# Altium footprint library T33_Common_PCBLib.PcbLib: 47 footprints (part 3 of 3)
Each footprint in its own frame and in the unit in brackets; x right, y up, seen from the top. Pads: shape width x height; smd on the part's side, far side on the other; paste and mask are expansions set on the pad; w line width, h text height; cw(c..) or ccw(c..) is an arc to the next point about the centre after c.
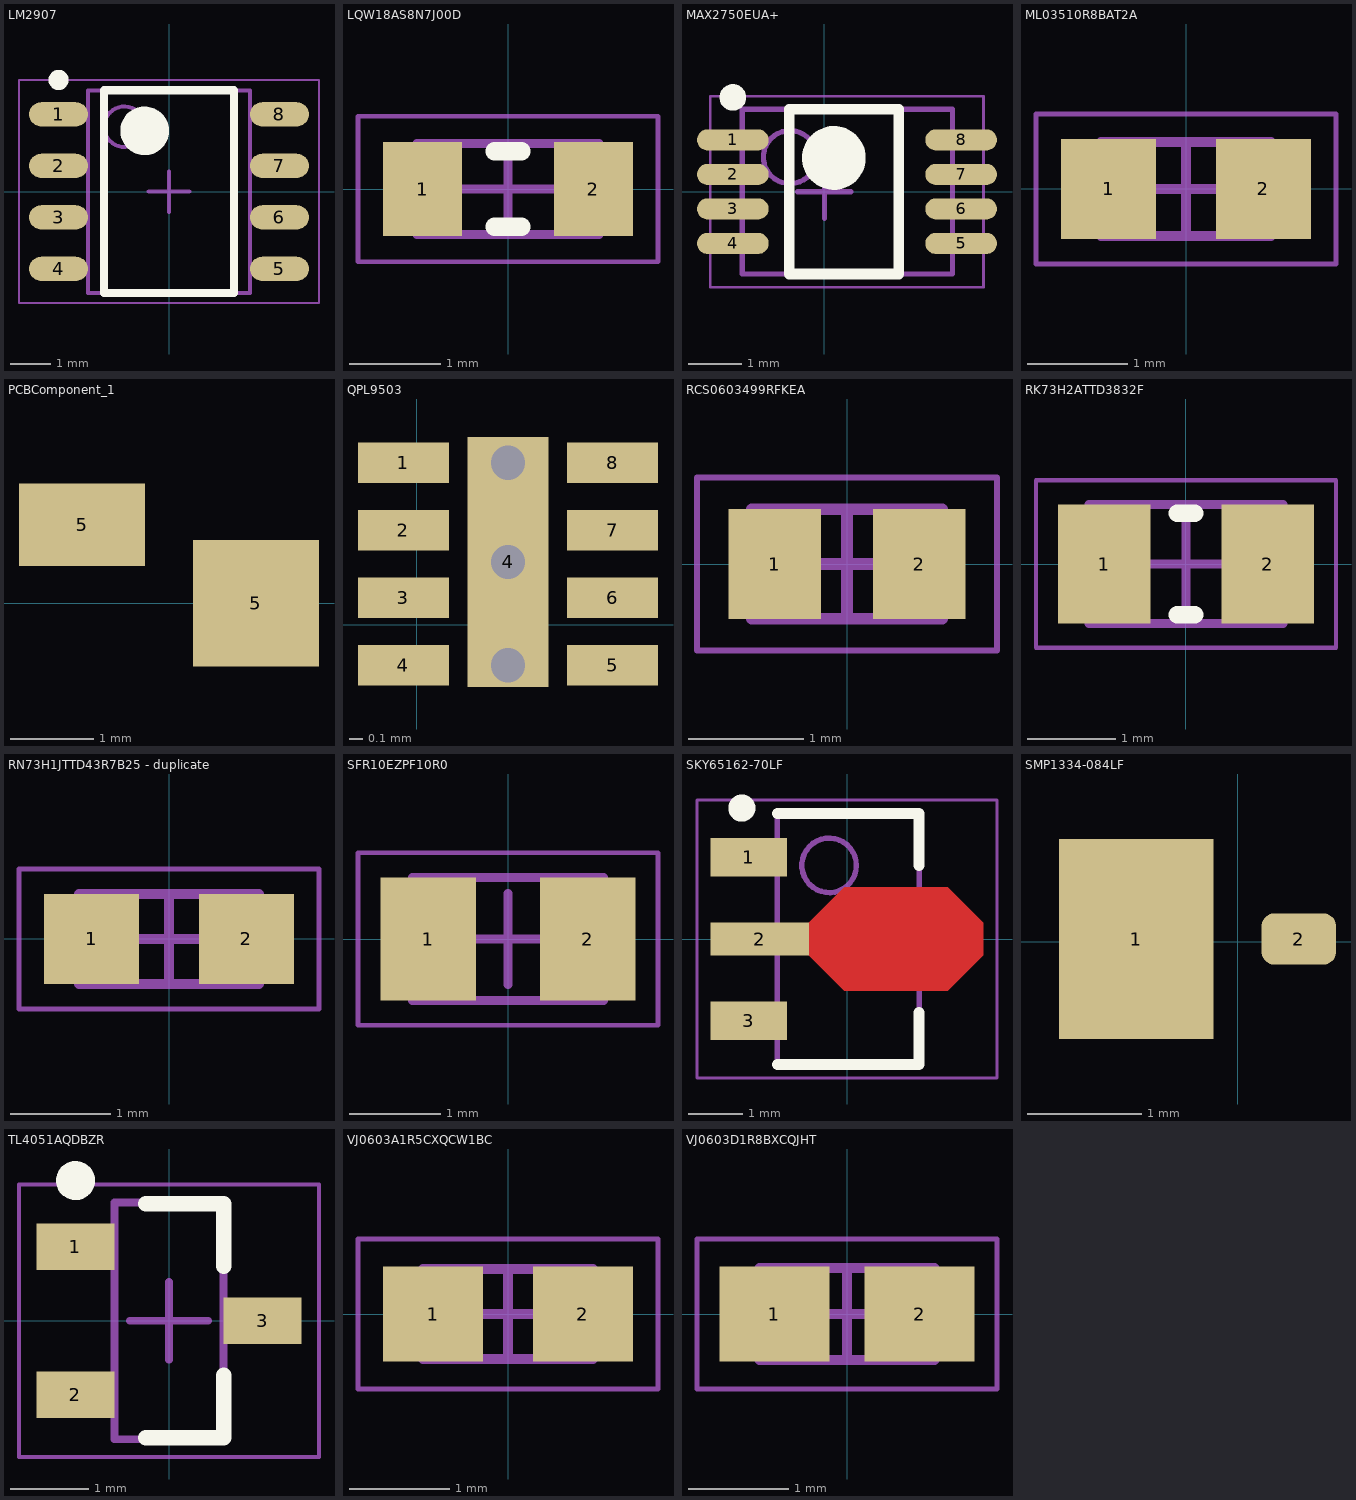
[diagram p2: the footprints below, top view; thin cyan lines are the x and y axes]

## LM2907 [mm] "Frequency to Voltage Converter"
height 1.75
pads (8):
  oval 1.45x0.6 smd: 1(-2.725,1.905) 2(-2.725,0.635) 3(-2.725,-0.635) 4(-2.725,-1.905) 5(2.725,-1.905) 6(2.725,-0.635) 7(2.725,0.635) 8(2.725,1.905)
Top Overlay:
  circle w0.25: c-2.725,2.755 r0.125
  circle w0.6: c-0.6,1.5 r0.3
  lines w0.2: -1.6,-2.5 -1.6,2.5 1.6,2.5 1.6,-2.5 -1.6,-2.5
Mechanical 13:
  circle w0.1: c-1.1,1.6 r0.5
  lines w0.1: -2,-2.5 -2,2.5 2,2.5 2,-2.5 -2,-2.5
Mechanical 15:
  lines w0.05: -3.7,-2.75 -3.7,2.75 3.7,2.75 3.7,-2.75 -3.7,-2.75
  lines w0.1: -0.5,0 0.5,0 ; 0,-0.5 0,0.5
3D body: height 1.75, standoff 0.1, extent -2,-2.5 2,2.5

## LQW18AS8N7J00D [mm] "8.7nH 0603"
height 0.94
pads (2):
  rect 0.87x1.03 smd: 1(-0.94,0) 2(0.94,0)
Top Overlay:
  lines w0.2: -0.15,-0.415 0.15,-0.415 ; -0.15,0.415 0.15,0.415
Mechanical 13:
  lines w0.1: -1,-0.5 1,-0.5 1,0.5 -1,0.5 -1,-0.5
Mechanical 15:
  lines w0.05: -1.65,-0.8 1.65,-0.8 1.65,0.8 -1.65,0.8 -1.65,-0.8
  lines w0.1: -0.5,0 0.5,0 ; 0,-0.5 0,0.5
3D body: height 0.94, standoff 0, extent 0.65,-0.5 1,0.5
3D body: height 0.94, standoff 0, extent -1,-0.5 -0.65,0.5
3D body: height 0.94, standoff 0, extent -0.65,-0.5 0.65,0.5

## MAX2750EUA+ [mm] "VCO Oscillators 2.4Ghz Monolithic Voltage-Controlled Oscillators"
height 1.1
pads (8):
  oval 1.35x0.4 smd: 1(-1.725,0.975) 2(-1.725,0.325) 3(-1.725,-0.325) 4(-1.725,-0.975) 5(2.575,-0.975) 6(2.575,-0.325) 7(2.575,0.325) 8(2.575,0.975)
Top Overlay:
  circle w0.6: c0.178,0.635 r0.3
  circle w0.25: c-1.725,1.775 r0.125
  lines w0.2: -0.66,-1.55 1.397,-1.55 1.397,1.55 -0.66,1.55 -0.66,-1.55
Mechanical 13:
  circle w0.1: c-0.65,0.65 r0.5
  lines w0.1: -1.55,-1.55 -1.55,1.55 2.413,1.55 2.413,-1.55 -1.55,-1.55
Mechanical 15:
  lines w0.05: -2.15,-1.8 2.997,-1.8 2.997,1.8 -2.15,1.8 -2.15,-1.8
  lines w0.1: -0.5,0 0.5,0 ; 0,-0.5 0,0.5
3D body: height 1.1, standoff 0.15, extent -1.55,-1.55 2.413,1.55

## ML03510R8BAT2A [mm] "MLCC - SMD/SMT 50V 0.8pF C0G 0603 0.1pF"
height 0.94
pads (2):
  rect 0.95x1 smd: 1(-0.775,0) 2(0.775,0)
Mechanical 13:
  lines w0.1: -0.85,-0.47 0.85,-0.47 0.85,0.47 -0.85,0.47 -0.85,-0.47
Mechanical 15:
  lines w0.05: -1.5,-0.75 1.5,-0.75 1.5,0.75 -1.5,0.75 -1.5,-0.75
  lines w0.1: -0.47,0 0.47,0 ; 0,-0.47 0,0.47
3D body: height 0.94, standoff 0, extent 0.5,-0.47 0.85,0.47
3D body: height 0.94, standoff 0, extent -0.85,-0.47 -0.5,0.47
3D body: height 0.94, standoff 0, extent -0.5,-0.47 0.5,0.47

## PCBComponent_1 [mm]
pads (2):
  rect 1.524x1 smd: 5(-3.15,0.95)
  rect 1.524x1.524 smd: 5(-1.05,0)

## QPL9503 [mm] "Ultra Low-Noise, Flat Gain LNA"
pads (9):
  rect 0.674x0.3 smd: 1(-0.1,1.2) 2(-0.1,0.7) 3(-0.1,0.2) 4(-0.1,-0.3) 5(1.45,-0.3) 6(1.45,0.2) 7(1.45,0.7) 8(1.45,1.2)
  rect 0.6x1.85 smd: 4(0.675,0.465)
via 0.675,0.465 diameter 0.254 hole 0.254
via 0.675,1.2 diameter 0.254 hole 0.254
via 0.675,-0.3 diameter 0.254 hole 0.254

## RCS0603499RFKEA [mm] "Thick Film Resistors - SMD 0.25watt 499ohms 1% 100ppm"
height 0.5
pads (2):
  rect 0.8x0.95 smd: 1(-0.625,0) 2(0.625,0)
Mechanical 13:
  lines w0.1: -0.825,-0.475 -0.825,0.475 0.825,0.475 0.825,-0.475 -0.825,-0.475
Mechanical 15:
  lines w0.05: -1.3,-0.75 -1.3,0.75 1.3,0.75 1.3,-0.75 -1.3,-0.75
  lines w0.1: -0.475,0 0.475,0 ; 0,-0.475 0,0.475
3D body: height 0.5, standoff 0, extent -0.525,-0.475 0.525,0.475
3D body: height 0.5, standoff 0, extent -0.825,-0.475 -0.525,0.475
3D body: height 0.5, standoff 0, extent 0.525,-0.475 0.825,0.475

## RK73H2ATTD3832F [mm] "Thick Film Resistors - SMD 1/4W 38.3K OHM 1%"
height 0.6
pads (2):
  rect 1.05x1.35 smd: 1(-0.925,0) 2(0.925,0)
Top Overlay:
  lines w0.2: -0.1,-0.575 0.1,-0.575 ; -0.1,0.575 0.1,0.575
Mechanical 13:
  lines w0.1: -1.1,-0.675 1.1,-0.675 1.1,0.675 -1.1,0.675 -1.1,-0.675
Mechanical 15:
  lines w0.05: -1.7,-0.95 1.7,-0.95 1.7,0.95 -1.7,0.95 -1.7,-0.95
  lines w0.1: -0.5,0 0.5,0 ; 0,-0.5 0,0.5
3D body: height 0.6, standoff 0, extent 0.75,-0.675 1.1,0.675
3D body: height 0.6, standoff 0, extent -1.1,-0.675 -0.75,0.675
3D body: height 0.6, standoff 0, extent -0.75,-0.675 0.75,0.675

## RN73H1JTTD43R7B25 - duplicate [mm] "Chip Resistor, 2-Leads, Body 1.60x0.80mm, IPC Medium Density"
height 0.55
pads (2):
  rect 0.95x0.9 smd: 1(-0.775,0) 2(0.775,0)
Mechanical 13:
  lines w0.1: -0.9,-0.45 -0.9,0.45 0.9,0.45 0.9,-0.45 -0.9,-0.45
Mechanical 15:
  lines w0.05: -1.5,-0.7 -1.5,0.7 1.5,0.7 1.5,-0.7 -1.5,-0.7
  lines w0.1: -0.45,0 0.45,0 ; 0,-0.45 0,0.45
3D body: height 0.55, standoff 0, extent -0.6,-0.45 0.6,0.45
3D body: height 0.55, standoff 0, extent -0.9,-0.45 -0.6,0.45
3D body: height 0.55, standoff 0, extent 0.6,-0.45 0.9,0.45

## SFR10EZPF10R0 [mm] "Thick Film Resistors - SMD 10ohm 0805 1%"
height 0.65
pads (2):
  rect 1.05x1.35 smd: 1(-0.875,0) 2(0.875,0)
Mechanical 13:
  lines w0.1: -1.05,-0.675 -1.05,0.675 1.05,0.675 1.05,-0.675 -1.05,-0.675
Mechanical 15:
  lines w0.05: -1.65,-0.95 -1.65,0.95 1.65,0.95 1.65,-0.95 -1.65,-0.95
  lines w0.1: -0.5,0 0.5,0 ; 0,-0.5 0,0.5
3D body: height 0.65, standoff 0, extent -0.65,-0.675 0.65,0.675
3D body: height 0.65, standoff 0, extent -1.05,-0.675 -0.65,0.675
3D body: height 0.65, standoff 0, extent 0.65,-0.675 1.05,0.675

## SKY65162-70LF [mm] "RF Amplifier 400-2700MHz NF 3.6dB Gain 24dB"
height 1.6
pads (3):
  rect 1.4x0.7 smd: 1(-1.8,1.5) 3(-1.8,-1.5)
  rect 1.8x0.6 smd: 2(-1.6,0)
Top Layer:
  region: -0.7,0.3 -0.05,0.95 1.85,0.95 2.5,0.3 2.5,-0.3 1.85,-0.95 -0.05,-0.95 -0.7,-0.3
Top Overlay:
  circle w0.25: c-1.927,2.4 r0.125
  lines w0.2: -1.278,-2.3 1.322,-2.3 1.322,-1.35 ; -1.278,2.3 1.322,2.3 1.322,1.35
Mechanical 13:
  circle w0.1: c-0.327,1.35 r0.5
  lines w0.1: -1.278,-2.3 -1.278,2.3 1.322,2.3 1.322,-2.3 -1.278,-2.3
Mechanical 15:
  lines w0.05: -2.75,-2.55 -2.75,2.55 2.75,2.55 2.75,-2.55 -2.75,-2.55
  lines w0.1: -0.477,0 0.523,0 ; 0.022,-0.5 0.022,0.5
3D body: height 1.6, standoff 0, extent -1.278,-2.3 1.322,2.3

## SMP1334-084LF [mm] "100 W High-Power Silicon PIN Diode"
height 1
pads (2):
  rect 1.35x1.75 smd: 1(-0.889,0.025)
  rrect50% 0.65x0.45 smd: 2(0.533,0.025)

## TL4051AQDBZR [mm] "Voltage References Precision Micropower Shunt Vltg Ref"
height 1.1
pads (3):
  rect 1x0.6 smd: 1(-1.2,0.95) 2(-1.2,-0.95) 3(1.2,0)
Top Overlay:
  circle w0.25: c-1.2,1.8 r0.125
  lines w0.2: -0.3,-1.5 0.7,-1.5 0.7,-0.7 ; -0.3,1.5 0.7,1.5 0.7,0.7
Mechanical 13:
  lines w0.1: -0.7,-1.52 0.7,-1.52 0.7,1.52 -0.7,1.52 -0.7,-1.52
Mechanical 15:
  lines w0.05: -1.925,-1.75 1.925,-1.75 1.925,1.75 -1.925,1.75 -1.925,-1.75
  lines w0.1: -0.5,0 0.5,0 ; 0,-0.5 0,0.5
3D body: height 1.1, standoff 0.05, extent -0.7,-1.52 0.7,1.52

## VJ0603A1R5CXQCW1BC [mm] "MLCC - SMD/SMT 0603 1.5pF 10volts C0G +/-0.25pF"
height 0.94
pads (2):
  rect 1x0.95 smd: 1(-0.75,0) 2(0.75,0)
Mechanical 13:
  lines w0.1: -0.85,-0.45 -0.85,0.45 0.85,0.45 0.85,-0.45 -0.85,-0.45
Mechanical 15:
  lines w0.05: -1.5,-0.75 -1.5,0.75 1.5,0.75 1.5,-0.75 -1.5,-0.75
  lines w0.1: -0.45,0 0.45,0 ; 0,-0.45 0,0.45
3D body: height 0.94, standoff 0, extent -0.47,-0.45 0.47,0.45
3D body: height 0.94, standoff 0, extent -0.85,-0.45 -0.47,0.45
3D body: height 0.94, standoff 0, extent 0.47,-0.45 0.85,0.45

## VJ0603D1R8BXCQJHT [mm] "Multilayer Ceramic Capacitors MLCC - SMD/SMT 1.8pF 200V 0.1% C0G"
height 0.94
pads (2):
  rect 1.1x0.95 smd: 1(-0.725,0) 2(0.725,0)
Mechanical 13:
  lines w0.1: -0.875,-0.46 0.875,-0.46 0.875,0.46 -0.875,0.46 -0.875,-0.46
Mechanical 15:
  lines w0.05: -1.5,-0.75 1.5,-0.75 1.5,0.75 -1.5,0.75 -1.5,-0.75
  lines w0.1: -0.46,0 0.46,0 ; 0,-0.46 0,0.46
3D body: height 0.94, standoff 0, extent 0.475,-0.46 0.875,0.46
3D body: height 0.94, standoff 0, extent -0.875,-0.46 -0.475,0.46
3D body: height 0.94, standoff 0, extent -0.475,-0.46 0.475,0.46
